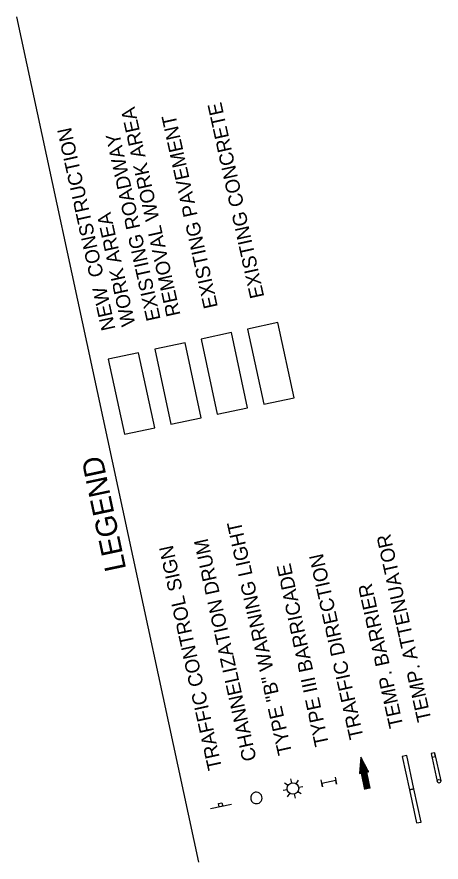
# Model space of a CAD drawing. Extents: x 1795987 to 1799700, y 243690 to 251545.
# Drawn here: x 1799466.6 to 1799700.4, y 250222 to 250687.4 of the extents above; entities that cross this region are included whole.
import ezdxf

# ---------------------------------------------------------------- set-up
doc = ezdxf.new("R2010")
doc.units = 0
for name, color, linetype in [('Level 23', 7, 'Continuous'), ('Level 31', 7, 'Continuous'), ('Prop_Horiz Alignment', 7, 'Continuous')]:
    doc.layers.add(name, color=color, linetype=linetype)

# ---------------------------------------------------------------- blocks, each defined once
blk = doc.blocks.new('T21LR')
at = {"layer": 'Level 23'}
for p, q in [((0, 2), (31.5, 2)), ((0, -2), (31.5, -2))]:
    blk.add_line(p, q, dxfattribs=at)
blk.add_lwpolyline([(0, -2), (4, -2), (4, 2), (0, 2)], close=True, dxfattribs=at)
blk.add_circle((31.5, 0), 2, dxfattribs=at)

msp = doc.modelspace()

# ---------------------------------------------------------------- linework, layer by layer
at = {"layer": 'Level 31'}
for p, q in [((1799566.87, 250222.02), (1799466.61, 250687.41)), ((1799656.18, 250279.76), (1799655.44, 250270.78)), ((1799660.34, 250271.77), (1799656.18, 250279.76)), ((1799655.44, 250270.78), (1799656.36, 250270.97)), ((1799656.36, 250270.97), (1799658.16, 250262.06)), ((1799659.42, 250271.58), (1799660.34, 250271.77)), ((1799661.22, 250262.68), (1799659.42, 250271.58)), ((1799618.03, 250265.65), (1799617.55, 250267.9)), ((1799621.69, 250267.15), (1799620.44, 250265.21)), ((1799615.58, 250261.85), (1799613.32, 250261.36)), ((1799616.02, 250264.26), (1799614.08, 250265.51)), ((1799621.83, 250263.2), (1799624.09, 250263.68)), ((1799615.72, 250257.9), (1799616.97, 250259.84)), ((1799619.38, 250259.4), (1799619.86, 250257.14)), ((1799623.33, 250259.54), (1799621.39, 250260.79)), ((1799584.79, 250253.8), (1799573.35, 250251.34))]:
    msp.add_line(p, q, dxfattribs=at)
for points in [[(1799619.32, 250477.73), (1799610.41, 250519.05), (1799593.73, 250515.46), (1799602.63, 250474.13)], [(1799593.74, 250472.22), (1799584.84, 250513.54), (1799568.15, 250509.95), (1799577.05, 250468.62)], [(1799568.16, 250466.71), (1799559.26, 250508.03), (1799542.57, 250504.44), (1799551.47, 250463.11)], [(1799542.58, 250461.2), (1799533.68, 250502.52), (1799516.99, 250498.93), (1799525.9, 250457.6)], [(1799681.4, 250280.73), (1799678.95, 250280.21), (1799682.9, 250261.88), (1799685.35, 250262.41)], [(1799685.35, 250262.41), (1799682.9, 250261.88), (1799686.85, 250243.55), (1799689.3, 250244.08)], [(1799578.11, 250252.36), (1799577.7, 250254.27), (1799579.61, 250254.68), (1799580.02, 250252.77)]]:
    msp.add_lwpolyline(points, close=True, dxfattribs=at)
for points in [[(1799655.84, 250275.68), (1799658.57, 250262.15)], [(1799655.92, 250276.61), (1799658.83, 250262.2)], [(1799656, 250277.54), (1799659.08, 250262.25)], [(1799656.07, 250278.48), (1799659.34, 250262.3)], [(1799656.15, 250279.41), (1799659.59, 250262.35)], [(1799656.45, 250279.24), (1799659.85, 250262.4)], [(1799656.88, 250278.41), (1799660.1, 250262.46)], [(1799657.32, 250277.58), (1799660.36, 250262.51)], [(1799657.75, 250276.75), (1799660.61, 250262.56)], [(1799658.18, 250275.92), (1799660.87, 250262.61)], [(1799655.46, 250271.01), (1799655.5, 250270.79)], [(1799655.53, 250271.95), (1799655.76, 250270.84)], [(1799655.61, 250272.88), (1799656.01, 250270.9)], [(1799655.69, 250273.81), (1799656.27, 250270.95)], [(1799655.77, 250274.74), (1799658.32, 250262.1)], [(1799658.61, 250275.09), (1799661.12, 250262.66)], [(1799659.05, 250274.26), (1799659.58, 250271.61)], [(1799659.48, 250273.43), (1799659.83, 250271.67)], [(1799659.91, 250272.6), (1799660.09, 250271.72)], [(1799641.91, 250268.81), (1799642.67, 250264.98), (1799642.29, 250266.89), (1799634.64, 250265.38), (1799635.02, 250263.46), (1799634.26, 250267.29)]]:
    msp.add_lwpolyline(points, dxfattribs=at)
msp.add_circle((1799618.71, 250262.52), 3.19, dxfattribs=at)
for start, end in [(102.1577, 282.1577), (282.1577, 102.1577)]:
    msp.add_arc((1799598.56, 250257.35), 3.18, start, end, dxfattribs=at)
at = {"layer": 'Prop_Horiz Alignment'}
msp.add_lwpolyline([(1799577.05, 250468.62), (1799593.74, 250472.22), (1799584.84, 250513.54), (1799568.15, 250509.95), (1799577.05, 250468.62)], dxfattribs=at)

# ---------------------------------------------------------------- block references
at = {"layer": 'Level 31', "xscale": 0.5000000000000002, "yscale": 0.5000000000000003, "rotation": -77.69303510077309}
msp.add_blockref('T21LR', (1799695.82, 250281.94), dxfattribs=at)

# ---------------------------------------------------------------- texts
at = {"layer": 'Level 31'}
for s, height, rotation, p in [('REMOVAL WORK AREA', 7.7999, 102.4707, (1799556.81, 250523.37)), ('EXISTING CONCRETE', 7.7999, 102.4707, (1799602.95, 250533.35)), ('EXISTING PAVEMENT', 7.7999, 102.4707, (1799577.39, 250527.76)), ('NEW  CONSTRUCTION', 7.7999, 102.4707, (1799520.99, 250515.6)), ('EXISTING ROADWAY', 7.7999, 102.4707, (1799545.83, 250520.95)), ('WORK AREA', 7.8, 102.4707, (1799531.97, 250518.02)), ('LEGEND', 11.7, 101.9916, (1799526.88, 250383.46)), ('TYPE "B" WARNING LIGHT', 7.7999, 102.4707, (1799618.28, 250281.94)), ('TEMP. ATTENUATOR', 7.7999, 102.4707, (1799695.06, 250300.2)), ('CHANNELIZATION DRUM', 7.7999, 102.4707, (1799598.71, 250278.49)), ('TRAFFIC CONTROL SIGN', 7.7999, 102.4707, (1799579.72, 250273.64)), ('TRAFFIC DIRECTION', 7.7999, 102.4707, (1799657.67, 250290.57)), ('TYPE III BARRICADE', 7.7999, 101.9916, (1799638.6, 250286.63)), ('TEMP. BARRIER', 7.7999, 102.4707, (1799679.59, 250296.81))]:
    msp.add_text(s, height=height, rotation=rotation, dxfattribs=at).set_placement(p)

doc.saveas('drawing.dxf')
